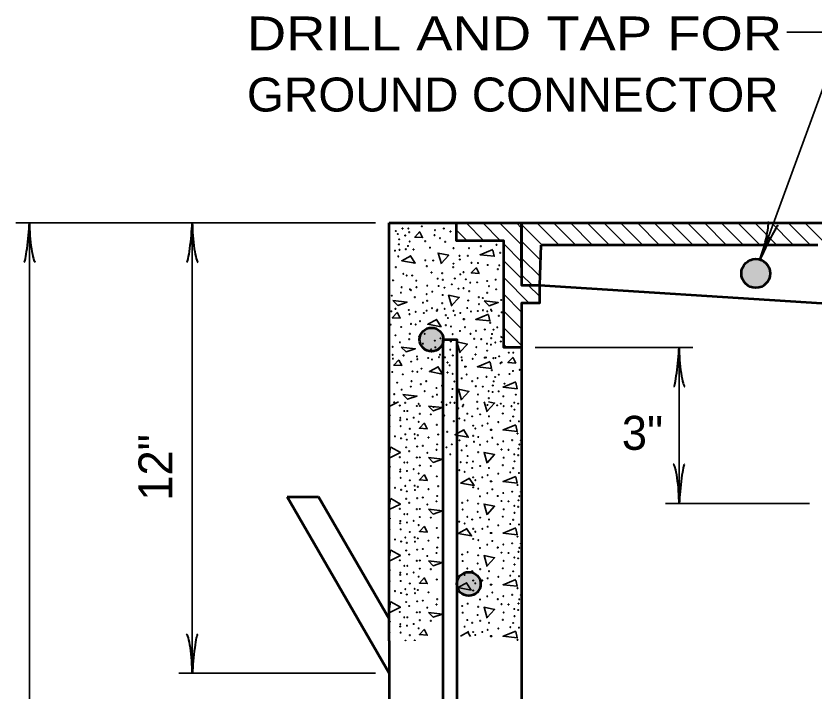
# Model space of a CAD drawing. Extents: x 788 to 1469, y -1 to 439.
# Drawn here: x 856.9 to 915.7, y 161.4 to 211.1 of the extents above; entities that cross this region are included whole.
import ezdxf

# ---------------------------------------------------------------- set-up
doc = ezdxf.new("R2010")
doc.units = 0
doc.layers.add('1', color=7, linetype='Continuous', lineweight=35)

msp = doc.modelspace()

# ---------------------------------------------------------------- hatches: boundary and pattern name
at = {"layer": '1'}
for points in [[(912.451, 192.159, 1), (910.325, 192.159, 1)], [(888.356, 187.287, 1), (886.612, 187.287, 1)], [(891.105, 169.287, 1), (889.352, 169.287, 1)]]:
    msp.add_hatch(color=256, dxfattribs=at).paths.add_polyline_path(points)

# ---------------------------------------------------------------- linework, layer by layer
for p, q in [((883.356, 195.872), (856.856, 195.872)), ((857.856, 195.872), (857.856, 121.703)), ((869.856, 195.872), (869.856, 162.703)), ((890.111, 194.562), (889.323, 195.35)), ((891.346, 194.562), (890.036, 195.872)), ((892.581, 194.562), (891.271, 195.872)), ((894.126, 194.252), (892.506, 195.872)), ((894.126, 195.487), (893.741, 195.872)), ((894.126, 195.762), (895.653, 194.235)), ((895.251, 195.872), (896.888, 194.235)), ((896.486, 195.872), (898.123, 194.235)), ((897.721, 195.872), (899.358, 194.235)), ((898.956, 195.872), (900.593, 194.235)), ((900.191, 195.872), (901.828, 194.235)), ((901.426, 195.872), (903.063, 194.235)), ((902.661, 195.872), (904.298, 194.235)), ((903.896, 195.872), (905.533, 194.235)), ((905.131, 195.872), (906.768, 194.235)), ((906.366, 195.872), (908.003, 194.235)), ((907.601, 195.872), (909.238, 194.235)), ((908.836, 195.872), (910.473, 194.235)), ((910.07, 195.872), (911.708, 194.235)), ((911.306, 195.872), (912.943, 194.235)), ((912.54, 195.872), (914.178, 194.235)), ((913.775, 195.872), (915.413, 194.235)), ((915.011, 195.872), (918.052, 192.831)), ((894.126, 193.017), (892.816, 194.327)), ((894.126, 194.527), (895.507, 193.145)), ((894.126, 191.782), (892.816, 193.092)), ((894.126, 193.292), (895.462, 191.956)), ((894.696, 189.978), (892.816, 191.857)), ((894.126, 192.057), (894.895, 191.287)), ((895.436, 190.472), (894.621, 191.287)), ((894.126, 189.312), (892.816, 190.622)), ((894.126, 188.077), (892.816, 189.387)), ((894.126, 186.842), (892.816, 188.152)), ((892.567, 187.515), (892.816, 187.373)), ((893.03, 186.703), (892.816, 186.917)), ((895.126, 186.703), (906.741, 186.703)), ((905.741, 175.212), (905.741, 186.703)), ((885.059, 182.703), (884.356, 182.36)), ((884.356, 182.483), (884.388, 182.703)), ((891.597, 181.971), (891.378, 182.703)), ((884.356, 178.683), (884.457, 179.391)), ((884.356, 174.883), (884.457, 175.591)), ((915.356, 175.212), (904.741, 175.212)), ((884.356, 171.083), (884.457, 171.791)), ((884.356, 167.283), (884.457, 167.991)), ((890.225, 165.779), (889.623, 165.45)), ((890.354, 165.413), (890.13, 165.762)), ((883.356, 162.703), (868.856, 162.703))]:
    msp.add_line(p, q, dxfattribs=at)
at = {"layer": '1', "lineweight": 53}
for p, q in [((884.356, 165.102), (884.356, 195.872)), ((894.126, 195.872), (939.973, 195.872)), ((894.126, 192.597), (894.126, 195.872)), ((895.549, 194.235), (895.436, 191.287)), ((915.95, 194.235), (895.549, 194.235)), ((895.436, 191.287), (916.244, 189.978)), ((894.126, 186.703), (894.126, 165.102)), ((884.356, 162.703), (876.856, 175.703)), ((876.856, 175.703), (879.165, 175.703)), ((884.356, 166.705), (879.165, 175.703)), ((884.356, 165.102), (884.356, 136.23)), ((894.126, 165.102), (894.126, 131.703))]:
    msp.add_line(p, q, dxfattribs=at)
at = {"layer": '1'}
for points in [[(911.684, 193.114), (917.856, 209.928), (913.665, 209.928)], [(886.631, 195.238), (886.251, 194.838), (886.832, 194.798), (886.631, 195.198)], [(888.213, 192.856), (887.973, 193.656), (888.753, 193.496), (888.193, 192.896)], [(892.01, 193.918), (891.07, 193.538), (892.11, 193.418), (892.01, 193.879)], [(885.956, 193.451), (885.296, 193.091), (886.276, 192.911), (885.916, 193.471)], [(890.798, 192.595), (890.418, 192.195), (890.997, 192.155), (890.798, 192.555)], [(888.985, 189.746), (888.745, 190.546), (889.525, 190.386), (888.965, 189.786)], [(884.967, 189.295), (884.587, 188.895), (885.167, 188.855), (884.967, 189.255)], [(891.687, 189.155), (890.747, 188.775), (891.787, 188.655), (891.687, 189.115)], [(887.867, 188.775), (887.207, 188.415), (888.187, 188.235), (887.827, 188.795)], [(889.587, 186.315), (889.347, 187.115), (890.127, 186.955), (889.567, 186.355)], [(893.5, 185.988), (893.12, 185.588), (893.7, 185.548), (893.5, 185.948)], [(885.087, 185.805), (884.707, 185.405), (885.287, 185.365), (885.087, 185.765)], [(887.987, 185.285), (887.327, 184.925), (888.307, 184.745), (887.947, 185.305)], [(891.807, 185.665), (890.867, 185.285), (891.907, 185.165), (891.807, 185.625)], [(893.697, 184.161), (892.757, 183.781), (893.797, 183.661), (893.697, 184.121)], [(889.707, 182.825), (889.467, 183.625), (890.247, 183.465), (889.687, 182.865)], [(891.688, 182.703), (892.137, 182.611), (891.577, 182.011)], [(886.977, 181.151), (886.597, 180.751), (887.177, 180.711), (886.977, 181.111)], [(889.877, 180.631), (889.217, 180.271), (890.197, 180.091), (889.837, 180.651)], [(893.697, 181.011), (892.757, 180.631), (893.797, 180.511), (893.697, 180.971)], [(884.497, 179.371), (885.197, 178.971), (884.356, 178.56)], [(891.597, 178.171), (891.357, 178.971), (892.137, 178.811), (891.577, 178.211)], [(886.977, 177.351), (886.597, 176.951), (887.177, 176.911), (886.977, 177.311)], [(890.298, 177.069), (889.638, 176.709), (890.618, 176.529), (890.258, 177.089)], [(893.697, 177.211), (892.757, 176.831), (893.797, 176.711), (893.697, 177.171)], [(884.497, 175.571), (885.197, 175.171), (884.356, 174.76)], [(891.597, 174.371), (891.357, 175.171), (892.137, 175.011), (891.577, 174.411)], [(886.977, 173.551), (886.597, 173.151), (887.177, 173.111), (886.977, 173.511)], [(890.115, 173.36), (889.455, 173), (890.435, 172.82), (890.075, 173.38)], [(893.697, 173.411), (892.757, 173.031), (893.797, 172.911), (893.697, 173.371)], [(884.497, 171.771), (885.197, 171.371), (884.356, 170.96)], [(891.597, 170.571), (891.357, 171.371), (892.137, 171.211), (891.577, 170.611)], [(886.977, 169.751), (886.597, 169.351), (887.177, 169.311), (886.977, 169.711)], [(893.697, 169.611), (892.757, 169.231), (893.797, 169.111), (893.697, 169.571)], [(890.079, 169.377), (889.419, 169.017), (890.399, 168.837), (890.039, 169.397)], [(884.497, 167.971), (885.197, 167.571), (884.356, 167.16)], [(891.597, 166.771), (891.357, 167.571), (892.137, 167.411), (891.577, 166.811)], [(886.977, 165.951), (886.597, 165.551), (887.177, 165.511), (886.977, 165.911)], [(893.697, 165.811), (892.757, 165.431), (893.797, 165.311), (893.697, 165.771)]]:
    msp.add_lwpolyline(points, dxfattribs=at)
at = {"layer": '1', "lineweight": 53}
msp.add_lwpolyline([(884.356, 195.872), (894.126, 195.872), (894.126, 191.287), (895.436, 191.287), (895.436, 189.978), (894.126, 189.978), (894.126, 186.703), (892.816, 186.703), (892.816, 194.562), (889.323, 194.562), (889.323, 195.872)], dxfattribs=at)
at = {"layer": '1'}
for points in [[(884.645, 190.166), (885.685, 190.046), (885.005, 189.806)], [(891.364, 190.13), (892.404, 190.01), (891.724, 189.77)], [(885.247, 186.735), (886.287, 186.615), (885.607, 186.375)], [(885.367, 183.245), (886.407, 183.125), (885.727, 182.885)], [(887.257, 182.391), (888.297, 182.271), (887.617, 182.031)], [(887.257, 178.591), (888.297, 178.471), (887.617, 178.231)], [(887.257, 174.791), (888.297, 174.671), (887.617, 174.431)], [(887.257, 170.991), (888.297, 170.871), (887.617, 170.631)], [(887.257, 167.191), (888.297, 167.071), (887.617, 166.831)]]:
    msp.add_lwpolyline(points, close=True, dxfattribs=at)
at = {"layer": '1', "lineweight": 53}
msp.add_lwpolyline([(888.356, 126.703), (888.356, 187.287), (889.356, 187.287), (889.356, 127.703), (909.356, 127.703), (909.356, 126.703)], close=True, dxfattribs=at)
at = {"layer": '1'}
for centre in [(884.86, 195.28), (885.347, 195.463), (885.774, 195.463), (886.77, 195.626), (887.745, 195.341), (888.396, 195.463), (885.002, 195.056), (885.55, 194.955), (885.835, 195.199), (887.705, 194.975), (888.111, 194.751), (888.883, 195.239), (885.083, 194.304), (885.103, 194.67), (885.754, 194.182), (885.876, 194.507), (887.014, 194.528), (888.497, 194.487), (891.119, 194.162), (892.277, 194.263), (884.799, 193.837), (885.124, 193.898), (885.591, 193.938), (886.16, 193.918), (887.379, 194.06), (889.107, 194.02), (890.245, 194.02), (892.541, 193.674), (885.042, 193.41), (887.034, 193.125), (887.603, 193.105), (889.554, 193.45), (889.574, 193.186), (890.164, 193.45), (890.428, 192.942), (890.916, 192.922), (884.86, 192.617), (887.136, 192.698), (889.087, 192.617), (889.107, 192.881), (891.627, 192.779), (892.379, 192.475), (892.48, 192.759), (885.408, 192.129), (885.652, 192.007), (886.059, 192.007), (887.481, 192.231), (887.94, 191.775), (888.274, 192.17), (889.208, 191.783), (889.615, 192.088), (889.838, 192.251), (884.653, 191.643), (886.363, 191.621), (887.176, 191.255), (888.009, 191.234), (888.324, 191.683), (888.987, 191.351), (890.021, 191.722), (890.347, 191.478), (890.855, 191.499), (891.586, 191.6), (891.728, 191.214), (892.216, 191.702), (885.236, 190.741), (885.289, 191.139), (885.896, 190.991), (885.978, 190.927), (886.376, 191.139), (887.131, 190.635), (887.542, 190.808), (888.311, 190.569), (888.443, 191.112), (889.473, 191.031), (889.838, 191.072), (890.265, 190.848), (891.586, 190.726), (892.257, 190.991), (884.56, 190.516), (886.257, 190.41), (886.853, 189.999), (887.171, 190.145), (890.193, 190.158), (890.975, 190.41), (891.266, 190.344), (892.618, 190.198), (884.825, 189.548), (885.819, 189.469), (887.123, 189.419), (887.516, 189.601), (887.873, 189.402), (887.918, 189.485), (888.271, 189.972), (888.457, 189.548), (889.106, 189.402), (890.126, 189.614), (890.988, 189.893), (891.285, 189.445), (891.876, 189.482), (891.921, 189.406), (884.526, 189.366), (885.864, 189.154), (886.315, 189.326), (886.919, 189.243), (888.541, 189.088), (888.7, 188.875), (889.217, 189.088), (889.615, 189.247), (890.397, 189.353), (890.895, 189.389), (891.598, 189.362), (892.451, 189.034), (892.658, 189.296), (884.473, 188.385), (885.97, 188.438), (886.315, 188.398), (886.633, 188.637), (888.541, 188.345), (888.926, 188.252), (889.84, 188.783), (889.893, 188.783), (891.815, 188.517), (885.254, 188.212), (885.891, 187.709), (886.977, 187.709), (889.045, 187.682), (889.588, 187.921), (889.959, 188.199), (890.357, 187.709), (890.768, 187.934), (891.417, 188.027), (891.947, 187.695), (892.053, 188.014), (892.332, 188.186), (884.83, 187.603), (885.162, 187.086), (885.838, 187.311), (886.58, 187.497), (887.733, 187.205), (888.144, 187.377), (888.912, 187.139), (890.635, 187.338), (891.152, 187.311), (891.881, 187.391), (892.193, 187.068), (892.599, 187.149), (884.618, 186.754), (886.858, 186.98), (887.455, 186.569), (887.773, 186.714), (888.873, 186.542), (890.794, 186.728), (891.576, 186.98), (891.59, 186.463), (891.868, 186.913), (884.618, 186.158), (884.646, 185.875), (885.427, 186.118), (886.421, 186.038), (887.244, 185.928), (888.039, 185.995), (888.117, 186.171), (888.475, 185.972), (889.058, 186.118), (889.708, 185.972), (890.728, 186.184), (891.405, 185.955), (891.497, 185.959), (892.041, 185.915), (892.199, 185.932), (892.477, 186.052), (893.189, 186.316), (893.514, 186.316), (885.984, 185.663), (886.435, 185.836), (887.521, 185.813), (888.662, 185.597), (888.821, 185.385), (889.338, 185.597), (889.735, 185.756), (889.96, 185.292), (890.013, 185.292), (890.517, 185.862), (892.571, 185.544), (892.66, 185.604), (884.593, 184.894), (885.375, 184.722), (886.09, 184.947), (886.435, 184.908), (886.753, 185.146), (888.662, 184.855), (889.046, 184.762), (890.08, 184.709), (891.935, 185.027), (892.452, 184.696), (893.229, 184.75), (893.494, 184.974), (893.981, 185.055), (884.951, 184.112), (886.011, 184.218), (887.098, 184.218), (889.165, 184.192), (889.709, 184.43), (890.477, 184.218), (890.888, 184.444), (891.538, 184.537), (892.068, 184.205), (892.174, 184.523), (885.282, 183.595), (885.958, 183.821), (886.7, 184.006), (887.853, 183.714), (888.264, 183.887), (889.033, 183.648), (890.756, 183.847), (891.272, 183.821), (892.001, 183.9), (892.864, 184.039), (884.739, 183.264), (886.978, 183.489), (887.575, 183.078), (887.893, 183.224), (888.993, 183.052), (890.915, 183.237), (891.697, 183.489), (891.71, 182.972), (891.988, 183.423), (892.437, 183.47), (892.782, 183.104), (893.697, 183.226), (884.739, 182.667), (885.15, 182.423), (885.547, 182.627), (886.403, 182.394), (886.541, 182.548), (886.629, 182.409), (888.238, 182.68), (888.595, 182.482), (888.869, 182.635), (889.178, 182.627), (889.783, 182.37), (889.828, 182.482), (890.848, 182.694), (891.617, 182.468), (892.32, 182.442), (892.598, 182.561), (892.805, 182.383), (893.38, 182.376), (893.587, 182.635), (893.878, 182.568), (885.482, 182.025), (885.707, 182.025), (886.629, 181.813), (887.438, 181.773), (887.641, 182.323), (889.465, 182.224), (890.128, 181.826), (890.883, 182.197), (891.069, 181.773), (892.739, 181.839), (893.6, 182.118), (884.408, 181.707), (885.177, 181.354), (885.19, 181.521), (885.68, 181.407), (886.171, 181.534), (886.536, 181.221), (888.325, 181.181), (888.431, 181.693), (889.134, 181.274), (889.531, 181.468), (889.929, 181.34), (890.486, 181.627), (891.718, 181.627), (892.407, 181.208), (893.295, 181.301), (893.507, 181.614), (893.931, 181.261), (885.217, 180.903), (885.892, 180.717), (887.875, 181.009), (890.552, 180.943), (890.711, 180.73), (891.228, 180.943), (891.625, 181.102), (891.851, 180.638), (891.904, 180.638), (884.792, 180.16), (885.243, 180.015), (885.561, 180.306), (886.25, 180.32), (886.264, 180.001), (886.483, 180.24), (887.265, 180.068), (887.981, 180.293), (888.325, 180.253), (888.643, 180.492), (890.552, 180.2), (890.936, 180.107), (891.97, 180.054), (893.825, 180.373), (885.667, 179.909), (886.423, 179.405), (886.841, 179.458), (887.901, 179.564), (888.988, 179.564), (889.548, 179.864), (890.064, 179.453), (890.613, 179.759), (891.056, 179.537), (891.599, 179.776), (892.368, 179.564), (892.778, 179.789), (893.428, 179.882), (893.958, 179.551), (894.064, 179.869), (885.614, 179.352), (885.839, 179.06), (887.172, 178.941), (887.848, 179.166), (888.59, 179.352), (888.869, 178.835), (889.706, 179.126), (890.923, 178.994), (892.646, 179.193), (893.163, 179.166), (893.587, 178.835), (893.892, 179.246), (885.15, 178.623), (885.482, 178.225), (885.707, 178.225), (886.403, 178.594), (886.629, 178.609), (889.632, 178.251), (890.086, 178.219), (890.149, 178.715), (890.549, 178.303), (892.805, 178.583), (893.6, 178.318), (893.878, 178.768), (884.408, 177.907), (885.19, 177.721), (886.171, 177.734), (886.629, 178.013), (887.438, 177.973), (889.531, 177.668), (890.486, 177.827), (891.069, 177.973), (891.718, 177.827), (892.739, 178.039), (893.507, 177.814), (885.177, 177.554), (885.217, 177.103), (885.68, 177.607), (886.536, 177.421), (887.875, 177.209), (889.929, 177.54), (890.552, 177.143), (891.228, 177.143), (891.625, 177.302), (892.407, 177.408), (893.295, 177.501), (893.931, 177.461), (885.561, 176.506), (885.892, 176.917), (886.25, 176.52), (887.981, 176.493), (890.711, 176.93), (891.851, 176.838), (891.904, 176.838), (893.825, 176.573), (884.792, 176.36), (885.243, 176.215), (885.667, 176.109), (886.264, 176.201), (886.483, 176.44), (887.265, 176.268), (890.552, 176.4), (890.936, 176.307), (891.599, 175.976), (891.97, 176.254), (892.778, 175.989), (893.428, 176.082), (894.064, 176.069), (885.614, 175.552), (886.423, 175.605), (886.841, 175.658), (887.848, 175.366), (887.901, 175.764), (890.154, 175.432), (891.056, 175.737), (892.368, 175.764), (892.646, 175.393), (893.163, 175.366), (893.892, 175.446), (893.958, 175.751), (885.15, 174.823), (885.839, 175.26), (886.403, 174.794), (886.629, 174.809), (887.172, 175.141), (889.743, 175.26), (889.783, 174.77), (890.923, 175.194), (892.805, 174.783), (893.587, 175.035), (893.878, 174.968), (884.408, 174.107), (885.482, 174.425), (885.707, 174.425), (886.629, 174.213), (887.438, 174.173), (890.128, 174.226), (890.883, 174.597), (891.069, 174.173), (892.739, 174.239), (893.6, 174.518), (885.177, 173.754), (885.19, 173.921), (885.68, 173.807), (886.171, 173.934), (886.536, 173.621), (889.531, 173.868), (889.929, 173.74), (890.486, 174.027), (891.718, 174.027), (892.407, 173.608), (893.295, 173.701), (893.507, 174.014), (893.931, 173.661), (885.217, 173.303), (885.892, 173.117), (887.875, 173.409), (890.552, 173.343), (890.711, 173.13), (891.228, 173.343), (891.625, 173.502), (891.851, 173.038), (891.904, 173.038), (884.792, 172.56), (885.243, 172.415), (885.561, 172.706), (886.25, 172.72), (886.264, 172.401), (886.483, 172.64), (887.265, 172.468), (887.981, 172.693), (890.552, 172.6), (890.936, 172.507), (891.97, 172.454), (893.825, 172.773), (885.614, 171.752), (885.667, 172.309), (886.423, 171.805), (886.841, 171.858), (887.901, 171.964), (891.056, 171.937), (891.599, 172.176), (892.368, 171.964), (892.778, 172.189), (893.428, 172.282), (893.958, 171.951), (894.064, 172.269), (885.839, 171.46), (887.172, 171.341), (887.848, 171.566), (889.743, 171.46), (890.154, 171.632), (890.923, 171.394), (892.646, 171.593), (893.163, 171.566), (893.587, 171.235), (893.878, 171.168), (893.892, 171.646), (885.15, 171.023), (885.482, 170.625), (885.707, 170.625), (886.403, 170.994), (886.629, 171.009), (889.783, 170.97), (890.883, 170.797), (892.805, 170.983), (893.6, 170.718), (884.408, 170.307), (885.19, 170.121), (885.68, 170.007), (886.171, 170.134), (886.629, 170.413), (887.438, 170.373), (890.128, 170.426), (890.486, 170.227), (891.069, 170.373), (891.718, 170.227), (892.739, 170.439), (893.507, 170.214), (885.177, 169.954), (885.217, 169.503), (886.536, 169.821), (887.875, 169.609), (889.929, 169.94), (890.552, 169.543), (891.228, 169.543), (891.625, 169.702), (892.407, 169.808), (893.295, 169.901), (893.931, 169.861), (885.561, 168.906), (885.892, 169.317), (886.25, 168.92), (886.483, 168.84), (890.711, 169.33), (891.851, 169.238), (891.904, 169.238), (893.825, 168.973), (884.792, 168.76), (885.243, 168.615), (885.667, 168.509), (886.264, 168.601), (887.265, 168.668), (890.552, 168.8), (890.936, 168.707), (891.599, 168.376), (891.97, 168.654), (892.778, 168.389), (893.428, 168.482), (894.064, 168.469), (885.614, 167.952), (885.839, 167.66), (886.423, 168.005), (886.841, 168.058), (887.848, 167.766), (887.901, 168.164), (889.743, 167.66), (890.154, 167.832), (891.056, 168.137), (892.368, 168.164), (892.646, 167.793), (893.163, 167.766), (893.892, 167.846), (893.958, 168.151), (885.15, 167.223), (886.403, 167.194), (886.629, 167.209), (887.172, 167.541), (889.783, 167.17), (890.923, 167.594), (892.805, 167.183), (893.587, 167.435), (893.878, 167.368), (884.408, 166.507), (885.482, 166.825), (885.707, 166.825), (886.629, 166.613), (887.438, 166.573), (890.128, 166.626), (890.883, 166.997), (891.069, 166.573), (892.739, 166.639), (893.6, 166.918), (885.177, 166.154), (885.19, 166.321), (885.68, 166.207), (886.171, 166.334), (886.536, 166.021), (889.929, 166.14), (890.486, 166.427), (891.625, 165.902), (891.718, 166.427), (892.407, 166.008), (893.295, 166.101), (893.507, 166.414), (893.931, 166.061), (885.217, 165.703), (885.892, 165.517), (890.552, 165.743), (890.711, 165.53), (891.228, 165.743), (891.851, 165.438), (891.904, 165.438), (893.825, 165.173)]:
    msp.add_circle(centre, 0.0265, dxfattribs=at)
at = {"layer": '1', "lineweight": 53}
for centre, radius in [((911.388, 192.159), 1.063), ((887.484, 187.287), 0.872), ((890.228, 169.287), 0.877)]:
    msp.add_circle(centre, radius, dxfattribs=at)
at = {"layer": '1'}
for centre, start, end in [((884.382, 180.89), 196.73563, 163.26437), ((884.382, 177.09), 196.73563, 163.26437), ((884.382, 173.29), 196.73563, 163.26437), ((884.382, 169.49), 196.73563, 163.26437), ((884.382, 165.69), 196.73563, 163.26437), ((885.561, 165.106), 350.65784, 189.34216), ((886.25, 165.12), 318.40069, 221.59931)]:
    msp.add_arc(centre, 0.0265, start, end, dxfattribs=at)
at = {"layer": '1', "lineweight": 40}
for centre, major_axis, ratio, start_param, end_param in [((911.801, 194.233), (-0.469, -1.73), 0.122415, 0.896353, 3.141593), ((857.637, 194.743), (0.176, 1.756), 0.07063, 3.140715, 5.41811), ((858.124, 194.772), (-0.156, 1.786), 0.122415, 0.896353, 3.141593), ((869.637, 194.743), (0.176, 1.756), 0.07063, 3.140715, 5.41811), ((870.124, 194.772), (-0.156, 1.786), 0.122415, 0.896353, 3.141593), ((912.269, 194.093), (0.77, 1.588), 0.07063, 6.282307, 8.559703), ((905.522, 185.573), (0.176, 1.756), 0.07063, 3.140715, 5.41811), ((906.009, 185.603), (-0.156, 1.786), 0.122415, 0.896353, 3.141593), ((905.465, 176.303), (0.156, -1.786), 0.122415, 0.896353, 3.141593), ((905.953, 176.332), (-0.176, -1.756), 0.07063, 3.140715, 5.41811), ((869.58, 163.794), (0.156, -1.786), 0.122415, 0.896353, 3.141593), ((870.068, 163.823), (-0.176, -1.756), 0.07063, 3.140715, 5.41811)]:
    msp.add_ellipse(centre, major_axis=major_axis, ratio=ratio, start_param=start_param, end_param=end_param, dxfattribs=at)

# ---------------------------------------------------------------- texts
at = {"layer": '1'}
for s, width, p in [('DRILL AND TAP FOR', 1.2, (873.875, 208.583)), ('GROUND CONNECTOR', 1.05, (873.875, 204.083))]:
    msp.add_text(s, height=2.5, dxfattribs=dict(at, width=width)).set_placement(p)
msp.add_text('3"', height=2.5, dxfattribs=at).set_placement((901.513, 179.165))
msp.add_text('12"', height=2.5, rotation=90, dxfattribs=at).set_placement((868.388, 175.412))

doc.saveas('drawing.dxf')
